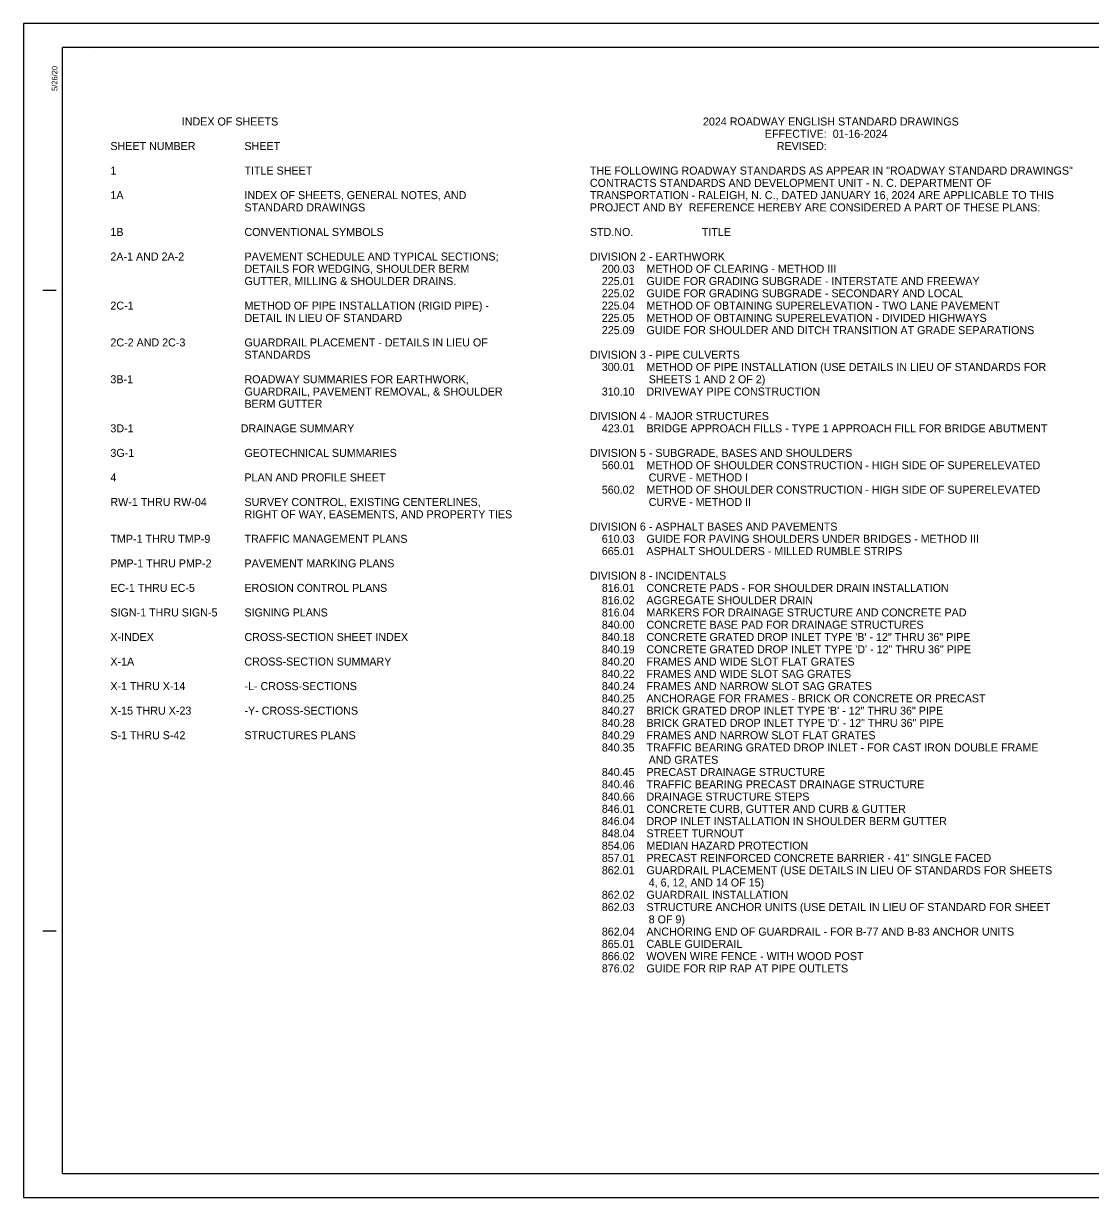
# Model space of a CAD drawing. Extents: x 1552903 to 1553045, y 811348 to 811440.
# Drawn here: x 1552903.2 to 1552986.4, y 811348.3 to 811440 of the extents above; entities that cross this region are included whole.
import ezdxf

# ---------------------------------------------------------------- set-up
doc = ezdxf.new("R2010")
doc.units = 0
for name, color, linetype in [('Prop Terminator CELL', 7, 'Continuous'), ('Sheet Plan CELL', 7, 'Continuous'), ('Typical Terminator CELL', 7, 'Continuous')]:
    doc.layers.add(name, color=color, linetype=linetype)

msp = doc.modelspace()

# ---------------------------------------------------------------- linework, layer by layer
at = {"layer": 'Prop Terminator CELL'}
for p, q in [((1552906.189, 811350.208), (1552906.191, 811438.123)), ((1553043.691, 811438.123), (1552906.191, 811438.123)), ((1552908.688, 811437.709), (1552908.688, 811437.709)), ((1552904.65, 811419.165), (1552905.693, 811419.168)), ((1552904.652, 811369.166), (1552905.694, 811369.165)), ((1552906.189, 811350.208), (1553043.689, 811350.208)), ((1552908.688, 811350.209), (1552908.688, 811350.209))]:
    msp.add_line(p, q, dxfattribs=at)
at = {"layer": 'Typical Terminator CELL'}
for p, q in [((1553044.816, 811439.998), (1552903.151, 811439.998)), ((1552903.151, 811439.998), (1552903.151, 811348.333)), ((1552903.151, 811348.333), (1553044.816, 811348.333))]:
    msp.add_line(p, q, dxfattribs=at)

# ---------------------------------------------------------------- texts
at = {"layer": 'Prop Terminator CELL'}
msp.add_text('5/26/20', height=0.4375, rotation=90, dxfattribs=at).set_placement((1552905.801, 811434.729))
at = {"layer": 'Sheet Plan CELL'}
for s, p in [('                        INDEX OF SHEETS ', (1552909.937, 811432.033)), ('                                      2024 ROADWAY ENGLISH STANDARD DRAWINGS', (1552947.367, 811432.033)), ('     EFFECTIVE:  01-16-2024       ', (1552959.867, 811431.075)), ('SHEET NUMBER', (1552909.937, 811430.117)), ('  SHEET   ', (1552919.937, 811430.117)), ('         REVISED:', (1552959.867, 811430.117)), ('1                       ', (1552909.937, 811428.2)), ('  TITLE SHEET', (1552919.937, 811428.2)), ('THE FOLLOWING ROADWAY STANDARDS AS APPEAR IN "ROADWAY STANDARD DRAWINGS" ', (1552947.367, 811428.2)), ('CONTRACTS STANDARDS AND DEVELOPMENT UNIT - N. C. DEPARTMENT OF ', (1552947.367, 811427.242)), ('1A                      ', (1552909.937, 811426.283)), ('  INDEX OF SHEETS, GENERAL NOTES, AND ', (1552919.937, 811426.283)), ('TRANSPORTATION - RALEIGH, N. C., DATED JANUARY 16, 2024 ARE APPLICABLE TO THIS ', (1552947.367, 811426.283)), ('  STANDARD DRAWINGS', (1552919.937, 811425.325)), ('PROJECT AND BY  REFERENCE HEREBY ARE CONSIDERED A PART OF THESE PLANS:', (1552947.367, 811425.325)), ('1B                      ', (1552909.937, 811423.408)), ('  CONVENTIONAL SYMBOLS', (1552919.937, 811423.408)), ('STD.NO.                       TITLE', (1552947.367, 811423.408)), ('2A-1 AND 2A-2           ', (1552909.937, 811421.492)), ('  PAVEMENT SCHEDULE AND TYPICAL SECTIONS; ', (1552919.937, 811421.492)), ('DIVISION 2 - EARTHWORK', (1552947.367, 811421.492)), ('  DETAILS FOR WEDGING, SHOULDER BERM ', (1552919.937, 811420.533)), ('    200.03    METHOD OF CLEARING - METHOD III', (1552947.367, 811420.533)), ('  GUTTER, MILLING & SHOULDER DRAINS.', (1552919.937, 811419.575)), ('    225.01    GUIDE FOR GRADING SUBGRADE - INTERSTATE AND FREEWAY', (1552947.367, 811419.575)), ('    225.02    GUIDE FOR GRADING SUBGRADE - SECONDARY AND LOCAL', (1552947.367, 811418.617)), ('2C-1', (1552909.937, 811417.658)), ('  METHOD OF PIPE INSTALLATION (RIGID PIPE) - ', (1552919.937, 811417.658)), ('    225.04    METHOD OF OBTAINING SUPERELEVATION - TWO LANE PAVEMENT', (1552947.367, 811417.658)), ('  DETAIL IN LIEU OF STANDARD', (1552919.937, 811416.7)), ('    225.05    METHOD OF OBTAINING SUPERELEVATION - DIVIDED HIGHWAYS', (1552947.367, 811416.7)), ('    225.09    GUIDE FOR SHOULDER AND DITCH TRANSITION AT GRADE SEPARATIONS', (1552947.367, 811415.742)), ('2C-2 AND 2C-3', (1552909.937, 811414.783)), ('  GUARDRAIL PLACEMENT - DETAILS IN LIEU OF ', (1552919.937, 811414.783)), ('  STANDARDS', (1552919.937, 811413.825)), ('DIVISION 3 - PIPE CULVERTS', (1552947.367, 811413.825)), ('    300.01    METHOD OF PIPE INSTALLATION (USE DETAILS IN LIEU OF STANDARDS FOR ', (1552947.367, 811412.867)), ('3B-1 ', (1552909.937, 811411.908)), ('  ROADWAY SUMMARIES FOR EARTHWORK, ', (1552919.937, 811411.908)), ('         SHEETS 1 AND 2 OF 2)', (1552949.867, 811411.908)), ('  GUARDRAIL, PAVEMENT REMOVAL, & SHOULDER ', (1552919.937, 811410.95)), ('    310.10    DRIVEWAY PIPE CONSTRUCTION', (1552947.367, 811410.95)), ('  BERM GUTTER', (1552919.937, 811409.992)), ('DIVISION 4 - MAJOR STRUCTURES', (1552947.367, 811409.033)), ('3D-1                                    DRAINAGE SUMMARY', (1552909.937, 811408.075)), ('    423.01    BRIDGE APPROACH FILLS - TYPE 1 APPROACH FILL FOR BRIDGE ABUTMENT', (1552947.367, 811408.075)), ('3G-1', (1552909.937, 811406.158)), ('  GEOTECHNICAL SUMMARIES', (1552919.937, 811406.158)), ('DIVISION 5 - SUBGRADE, BASES AND SHOULDERS', (1552947.367, 811406.158)), ('    560.01    METHOD OF SHOULDER CONSTRUCTION - HIGH SIDE OF SUPERELEVATED ', (1552947.367, 811405.2)), ('4 ', (1552909.937, 811404.242)), ('  PLAN AND PROFILE SHEET', (1552919.937, 811404.242)), ('         CURVE - METHOD I', (1552949.867, 811404.242)), ('    560.02    METHOD OF SHOULDER CONSTRUCTION - HIGH SIDE OF SUPERELEVATED ', (1552947.367, 811403.283)), ('RW-1 THRU RW-04', (1552909.937, 811402.325)), ('  SURVEY CONTROL, EXISTING CENTERLINES, ', (1552919.937, 811402.325)), ('         CURVE - METHOD II', (1552949.867, 811402.325)), ('  RIGHT OF WAY, EASEMENTS, AND PROPERTY TIES', (1552919.937, 811401.367)), ('DIVISION 6 - ASPHALT BASES AND PAVEMENTS', (1552947.367, 811400.408)), ('TMP-1 THRU TMP-9', (1552909.937, 811399.45)), ('  TRAFFIC MANAGEMENT PLANS', (1552919.937, 811399.45)), ('    610.03    GUIDE FOR PAVING SHOULDERS UNDER BRIDGES - METHOD III', (1552947.367, 811399.45)), ('    665.01    ASPHALT SHOULDERS - MILLED RUMBLE STRIPS', (1552947.367, 811398.492)), ('PMP-1 THRU PMP-2', (1552909.937, 811397.533)), ('  PAVEMENT MARKING PLANS', (1552919.937, 811397.533)), ('DIVISION 8 - INCIDENTALS', (1552947.367, 811396.575)), ('EC-1 THRU EC-5', (1552909.937, 811395.617)), ('  EROSION CONTROL PLANS', (1552919.937, 811395.617)), ('    816.01    CONCRETE PADS - FOR SHOULDER DRAIN INSTALLATION', (1552947.367, 811395.617)), ('    816.02    AGGREGATE SHOULDER DRAIN', (1552947.367, 811394.658)), ('SIGN-1 THRU SIGN-5', (1552909.937, 811393.7)), ('  SIGNING PLANS', (1552919.937, 811393.7)), ('    816.04    MARKERS FOR DRAINAGE STRUCTURE AND CONCRETE PAD', (1552947.367, 811393.7)), ('    840.00    CONCRETE BASE PAD FOR DRAINAGE STRUCTURES', (1552947.367, 811392.742)), ('X-INDEX', (1552909.937, 811391.783)), ('  CROSS-SECTION SHEET INDEX', (1552919.937, 811391.783)), ('    840.18    CONCRETE GRATED DROP INLET TYPE \'B\' - 12" THRU 36" PIPE', (1552947.367, 811391.783)), ('    840.19    CONCRETE GRATED DROP INLET TYPE \'D\' - 12" THRU 36" PIPE', (1552947.367, 811390.825)), ('X-1A', (1552909.937, 811389.867)), ('  CROSS-SECTION SUMMARY', (1552919.937, 811389.867)), ('    840.20    FRAMES AND WIDE SLOT FLAT GRATES', (1552947.367, 811389.867)), ('    840.22    FRAMES AND WIDE SLOT SAG GRATES', (1552947.367, 811388.908)), ('X-1 THRU X-14            ', (1552909.937, 811387.95)), ('  -L- CROSS-SECTIONS', (1552919.937, 811387.95)), ('    840.24    FRAMES AND NARROW SLOT SAG GRATES', (1552947.367, 811387.95)), ('    840.25    ANCHORAGE FOR FRAMES - BRICK OR CONCRETE OR PRECAST', (1552947.367, 811386.992)), ('X-15 THRU X-23            ', (1552909.937, 811386.033)), ('  -Y- CROSS-SECTIONS', (1552919.937, 811386.033)), ('    840.27    BRICK GRATED DROP INLET TYPE \'B\' - 12" THRU 36" PIPE', (1552947.367, 811386.033)), ('    840.28    BRICK GRATED DROP INLET TYPE \'D\' - 12" THRU 36" PIPE', (1552947.367, 811385.075)), ('S-1 THRU S-42', (1552909.937, 811384.117)), ('  STRUCTURES PLANS', (1552919.937, 811384.117)), ('    840.29    FRAMES AND NARROW SLOT FLAT GRATES', (1552947.367, 811384.117)), ('    840.35    TRAFFIC BEARING GRATED DROP INLET - FOR CAST IRON DOUBLE FRAME ', (1552947.367, 811383.158)), ('         AND GRATES', (1552949.867, 811382.2)), ('    840.45    PRECAST DRAINAGE STRUCTURE', (1552947.367, 811381.242)), ('    840.46    TRAFFIC BEARING PRECAST DRAINAGE STRUCTURE', (1552947.367, 811380.283)), ('    840.66    DRAINAGE STRUCTURE STEPS', (1552947.367, 811379.325)), ('    846.01    CONCRETE CURB, GUTTER AND CURB & GUTTER', (1552947.367, 811378.367)), ('    846.04    DROP INLET INSTALLATION IN SHOULDER BERM GUTTER', (1552947.367, 811377.408)), ('    848.04    STREET TURNOUT', (1552947.367, 811376.45)), ('    854.06    MEDIAN HAZARD PROTECTION', (1552947.367, 811375.492)), ('    857.01    PRECAST REINFORCED CONCRETE BARRIER - 41" SINGLE FACED', (1552947.367, 811374.533)), ('    862.01    GUARDRAIL PLACEMENT (USE DETAILS IN LIEU OF STANDARDS FOR SHEETS ', (1552947.367, 811373.575)), ('         4, 6, 12, AND 14 OF 15)', (1552949.867, 811372.617)), ('    862.02    GUARDRAIL INSTALLATION', (1552947.367, 811371.658)), ('    862.03    STRUCTURE ANCHOR UNITS (USE DETAIL IN LIEU OF STANDARD FOR SHEET ', (1552947.367, 811370.7)), ('         8 OF 9)', (1552949.867, 811369.742)), ('    862.04    ANCHORING END OF GUARDRAIL - FOR B-77 AND B-83 ANCHOR UNITS', (1552947.367, 811368.783)), ('    865.01    CABLE GUIDERAIL', (1552947.367, 811367.825)), ('    866.02    WOVEN WIRE FENCE - WITH WOOD POST', (1552947.367, 811366.867)), ('    876.02    GUIDE FOR RIP RAP AT PIPE OUTLETS', (1552947.367, 811365.908))]:
    msp.add_text(s, height=0.625, dxfattribs=at).set_placement(p)

doc.saveas('drawing.dxf')
